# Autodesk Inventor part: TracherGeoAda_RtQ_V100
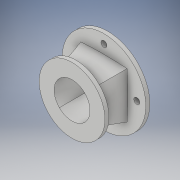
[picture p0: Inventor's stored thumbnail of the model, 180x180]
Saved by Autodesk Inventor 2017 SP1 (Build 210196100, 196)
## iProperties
Part Number: TracherGeoAda_RtQ_V100
Material: Generisch
Document SubType Name: Modeling
Designer: haesner
Density: 1 g/cm^3
Appearance: Vorgabe
Part Number: TracherGeoAda_RtQ_V100_3D-Druck
Author: haesner
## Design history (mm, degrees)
sketch "Skizze1"
  geometry: C1 r 9 at (0, 0); 1 further point
  constraints: 1 centre point, 1 coincident
  dimensions: "d0" = 18 diameter of C1
workplane "Arbeitsebene1"
sketch "Skizze2"
  geometry: L1 (-9, 9)-(9, 9); L2 (9, 9)-(9, -9); L3 (9, -9)-(-9, -9); L4 (-9, -9)-(-9, 9); L5 (-9, 9)-(9, -9); L6 (9, 9)-(-9, -9); 1 further point
  constraints: 12 end point, 2 midpoint, 2 parallel, 2 perpendicular, 1 horizontal
  dimensions: "d2" = 18 distance of L1.end L2.end
feature "Erhebung1" sketch "Skizze2" dims "d3" = 0, "d4" = 90 deg, "d5" = 0, "d6" = 90 deg
feature "Wandung1" dims "d7" = 3
sketch "Skizze3"
  geometry: C1 r 16.5 at (-4.057, -9.43); 4 further points
  constraints: 1 centre point, 4 other
  dimensions: "d8" = 33 diameter of C1
extrude "Extrusion1" join sketch "Skizze3" distance "d9" = 2; taper "d10" = 0 deg
sketch "Skizze4"
  geometry: L1 (-8.917, 3.28)-(-8.445, 21.274) reference; L2 (-8.445, 21.274)-(9.549, 20.802) reference; L3 (9.077, 2.808)-(-8.917, 3.28) reference; L4 (9.549, 20.802)-(9.077, 2.808) reference; C1 r 21 at (0.316, 12.041); 1 further point
  constraints: 1 centre point, 1 coincident
  dimensions: "d11" = 42 diameter of C1
extrude "Extrusion2" join sketch "Skizze4" distance "d12" = 2; taper "d13" = 0 deg
sketch "Skizze5"
  geometry: L1 (-16.5, 0)-(0, -16.5); L2 (0, -16.5)-(16.5, 0); L3 (16.5, 0)-(0, 16.5); L4 (0, 16.5)-(-16.5, 0); L5 (-29.4, 0)-(29.4, 0) reference; L6 (0, 29.4)-(0, -29.4) reference; 1 further point
  constraints: 8 end point, 3 point on line, 2 parallel, 2 perpendicular
  dimensions: "d14" = 16.5 distance from line of L1.start L6
hole "Bohrung1" sketch "Skizze5" at (-16.5, 0), (0, 16.5), (16.5, 0), (0, -16.5) diameter "d15" = 3; stored, may be unused: countersink angle "d19" = 90 deg, drill point angle "d21" = 118 deg; dims "d16" = 6, "d17" = 4, "d18" = 2, "d20" = 8
node "Volumenkörper1"
other parameters: "d1" = 18
